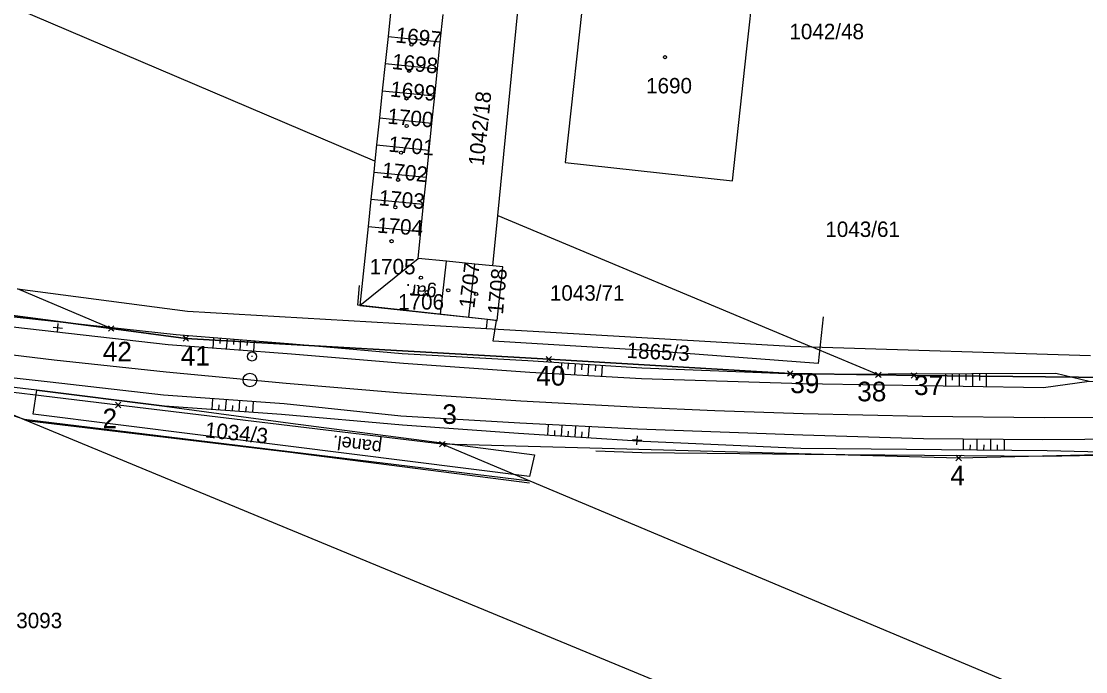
# Model space of a CAD drawing. Extents: x -779302 to -774398, y -1144902 to -1142831.
# Drawn here: x -775436.1 to -775318.8, y -1144493.5 to -1144421.9 of the extents above; entities that cross this region are included whole.
import ezdxf

# ---------------------------------------------------------------- set-up
doc = ezdxf.new("R2010")
doc.units = 0
for name, color, linetype in [('Hranice parcel', 7, 'Continuous'), ('legenda I_5_2 - Vrstva 53', 7, 'Continuous'), ('Parcelní čísla', 7, 'Continuous'), ('SŽDC', 7, 'Continuous'), ('zjednodus_g_situ-seda - Vrstva 1', 7, 'Continuous'), ('zjednodus_g_situ-seda - Vrstva 16', 7, 'Continuous'), ('zjednodus_g_situ-seda - Vrstva 17', 7, 'Continuous'), ('zjednodus_g_situ-seda - Vrstva 23', 7, 'Continuous'), ('zjednodus_g_situ-seda - Vrstva 48', 7, 'Continuous'), ('zjednodus_g_situ-seda - Vrstva 49', 7, 'Continuous'), ('zjednodus_g_situ-seda - Vrstva 59', 7, 'Continuous'), ('zjednodus_g_situ-seda - Vrstva 7', 7, 'Continuous'), ('Značky budov', 7, 'Continuous')]:
    doc.layers.add(name, color=color, linetype=linetype)

msp = doc.modelspace()

# ---------------------------------------------------------------- linework, layer by layer
at = {"layer": 'Hranice parcel'}
for p, q in [((-775383.57, -1144443.27), (-775380.75, -1144414.72)), ((-775395.35, -1144420.56), (-775395.66, -1144423.55)), ((-775389.9, -1144424.12), (-775389.59, -1144421.13)), ((-775395.66, -1144423.55), (-775395.97, -1144426.53)), ((-775395.66, -1144423.55), (-775389.9, -1144424.12)), ((-775390.2, -1144427.1), (-775389.9, -1144424.12)), ((-775395.97, -1144426.53), (-775396.29, -1144429.52)), ((-775395.97, -1144426.53), (-775390.2, -1144427.1)), ((-775390.52, -1144430.09), (-775390.2, -1144427.1)), ((-775396.29, -1144429.52), (-775396.6, -1144432.51)), ((-775396.29, -1144429.52), (-775390.52, -1144430.09)), ((-775390.82, -1144433.08), (-775390.52, -1144430.09)), ((-775396.6, -1144432.51), (-775396.92, -1144435.49)), ((-775396.6, -1144432.51), (-775390.82, -1144433.08)), ((-775391.12, -1144436.06), (-775390.82, -1144433.08)), ((-775396.92, -1144435.49), (-775397.11, -1144437.29)), ((-775396.92, -1144435.49), (-775391.12, -1144436.06)), ((-775391.44, -1144439.04), (-775391.12, -1144436.06)), ((-775397.11, -1144437.29), (-775397.23, -1144438.48)), ((-775397.23, -1144438.48), (-775397.55, -1144441.47)), ((-775397.23, -1144438.48), (-775391.44, -1144439.04)), ((-775391.74, -1144442.03), (-775391.44, -1144439.04)), ((-775397.55, -1144441.47), (-775397.86, -1144444.46)), ((-775397.55, -1144441.47), (-775391.74, -1144442.03)), ((-775392.05, -1144445.02), (-775391.74, -1144442.03)), ((-775384.12, -1144448.81), (-775383.57, -1144443.27)), ((-775383.57, -1144443.27), (-775348.99, -1144457.75)), ((-775397.86, -1144444.46), (-775398.78, -1144453.2)), ((-775397.86, -1144444.46), (-775392.05, -1144445.02)), ((-775392.35, -1144448), (-775392.05, -1144445.02)), ((-775398.78, -1144453.2), (-775392.35, -1144448)), ((-775389.23, -1144448.31), (-775392.35, -1144448)), ((-775426.17, -1144455.72), (-775474.88, -1144449.28)), ((-775389.89, -1144454.15), (-775389.23, -1144448.31)), ((-775386.1, -1144448.62), (-775389.23, -1144448.31)), ((-775386.75, -1144454.48), (-775386.1, -1144448.62)), ((-775384.12, -1144448.81), (-775386.1, -1144448.62)), ((-775426.17, -1144455.72), (-775436.47, -1144451.33)), ((-775398.78, -1144453.2), (-775389.89, -1144454.15)), ((-775389.89, -1144454.15), (-775386.75, -1144454.48)), ((-775386.75, -1144454.48), (-775384.7, -1144454.7)), ((-775384.8, -1144455.7), (-775384.7, -1144454.7)), ((-775348.99, -1144457.75), (-775318.25, -1144458.71)), ((-775341.64, -1144460.83), (-775348.99, -1144457.75)), ((-775445.43, -1144461.73), (-775435.74, -1144465.74)), ((-775380, -1144472.53), (-775435.74, -1144465.74)), ((-775435.74, -1144465.74), (-775366.41, -1144494.44)), ((-775380, -1144472.53), (-775389.68, -1144468.46)), ((-775253.51, -1144525.7), (-775380, -1144472.53))]:
    msp.add_line(p, q, dxfattribs=at)
for points in [[(-775397.11, -1144437.29), (-775575.13, -1144361.42), (-775643.03, -1144333.5), (-775681.69, -1144314.82), (-775705.2, -1144302.37), (-775726.91, -1144287.21)], [(-775355.32, -1144417.54), (-775373.75, -1144415.54), (-775373.98, -1144417.62), (-775376.13, -1144437.44), (-775357.7, -1144439.44), (-775356.16, -1144425.25), (-775355.32, -1144417.54)], [(-775384.7, -1144454.7), (-775383.62, -1144454.82), (-775383.02, -1144448.92), (-775384.12, -1144448.81)], [(-775436.47, -1144451.33), (-775417.75, -1144453.81), (-775384.8, -1144455.7)], [(-775341.64, -1144460.83), (-775351.35, -1144460.68), (-775377.95, -1144459.1), (-775417.93, -1144456.81), (-775426.17, -1144455.72)], [(-775384.8, -1144455.7), (-775377.77, -1144456.11), (-775351.31, -1144457.68), (-775348.99, -1144457.75)], [(-775254.16, -1144459.9), (-775301.48, -1144461.27), (-775337.71, -1144460.89), (-775341.64, -1144460.83)], [(-775389.68, -1144468.46), (-775425.39, -1144464.15), (-775445.43, -1144461.73)], [(-775204.62, -1144464.16), (-775217.76, -1144465.11), (-775237.91, -1144466.56), (-775289.7, -1144468.96), (-775332.79, -1144469.99), (-775389.68, -1144468.46)]]:
    msp.add_lwpolyline(points, dxfattribs=at)
at = {"layer": 'legenda I_5_2 - Vrstva 53'}
for points in [[(-775474.88, -1144449.28), (-775426.17, -1144455.72), (-775417.93, -1144456.81), (-775377.95, -1144459.1), (-775351.35, -1144460.68), (-775341.64, -1144460.83), (-775337.71, -1144460.89), (-775301.48, -1144461.27), (-775254.16, -1144459.9), (-775170.99, -1144453.66), (-775138.01, -1144449.91), (-775088.39, -1144447.82), (-775071.04, -1144440.88), (-775069.78, -1144440.38), (-775036.16, -1144437.94), (-775037.63, -1144440.85), (-775032.95, -1144440.83), (-775006.9, -1144440.82), (-775003.31, -1144440.57), (-774957.77, -1144437.47), (-774890.46, -1144432.61)], [(-774919.16, -1144442.27), (-774942.23, -1144444.12), (-775006.07, -1144448.84), (-775047.73, -1144454.47), (-775049.08, -1144458.29), (-775076.86, -1144459.23), (-775096.64, -1144457.51), (-775137.35, -1144459.01), (-775201.24, -1144463.92), (-775204.62, -1144464.16), (-775217.76, -1144465.11), (-775237.91, -1144466.56), (-775289.7, -1144468.96), (-775332.79, -1144469.99)], [(-775332.79, -1144469.99), (-775389.68, -1144468.46), (-775425.39, -1144464.15), (-775445.43, -1144461.73)]]:
    msp.add_lwpolyline(points, dxfattribs=at)
at = {"layer": 'SŽDC'}
for p, q in [((-775425.97, -1144455.92), (-775426.47, -1144455.42)), ((-775425.97, -1144455.52), (-775426.47, -1144456.02)), ((-775426.37, -1144455.92), (-775425.87, -1144455.42)), ((-775426.37, -1144455.52), (-775425.87, -1144456.02)), ((-775426.17, -1144455.72), (-775426.17, -1144455.72)), ((-775417.73, -1144457.01), (-775418.23, -1144456.51)), ((-775417.73, -1144456.61), (-775418.23, -1144457.11)), ((-775418.13, -1144457.01), (-775417.63, -1144456.51)), ((-775418.13, -1144456.61), (-775417.63, -1144457.11)), ((-775417.93, -1144456.81), (-775417.93, -1144456.81)), ((-775377.75, -1144459.3), (-775378.25, -1144458.8)), ((-775377.75, -1144458.9), (-775378.25, -1144459.4)), ((-775378.15, -1144459.3), (-775377.65, -1144458.8)), ((-775378.15, -1144458.9), (-775377.65, -1144459.4)), ((-775377.95, -1144459.1), (-775377.95, -1144459.1)), ((-775351.15, -1144460.88), (-775351.65, -1144460.38)), ((-775351.15, -1144460.48), (-775351.65, -1144460.98)), ((-775351.55, -1144460.88), (-775351.05, -1144460.38)), ((-775351.55, -1144460.48), (-775351.05, -1144460.98)), ((-775351.35, -1144460.68), (-775351.35, -1144460.68)), ((-775341.44, -1144461.03), (-775341.94, -1144460.53)), ((-775341.44, -1144460.63), (-775341.94, -1144461.13)), ((-775341.84, -1144461.03), (-775341.34, -1144460.53)), ((-775341.84, -1144460.63), (-775341.34, -1144461.13)), ((-775341.64, -1144460.83), (-775341.64, -1144460.83)), ((-775337.51, -1144461.09), (-775338.01, -1144460.59)), ((-775337.51, -1144460.69), (-775338.01, -1144461.19)), ((-775337.91, -1144461.09), (-775337.41, -1144460.59)), ((-775337.91, -1144460.69), (-775337.41, -1144461.19)), ((-775337.71, -1144460.89), (-775337.71, -1144460.89)), ((-775425.19, -1144464.35), (-775425.69, -1144463.85)), ((-775425.19, -1144463.95), (-775425.69, -1144464.45)), ((-775425.59, -1144464.35), (-775425.09, -1144463.85)), ((-775425.59, -1144463.95), (-775425.09, -1144464.45)), ((-775425.39, -1144464.15), (-775425.39, -1144464.15)), ((-775389.48, -1144468.66), (-775389.98, -1144468.16)), ((-775389.88, -1144468.66), (-775389.38, -1144468.16)), ((-775389.48, -1144468.26), (-775389.98, -1144468.76)), ((-775389.88, -1144468.26), (-775389.38, -1144468.76)), ((-775389.68, -1144468.46), (-775389.68, -1144468.46)), ((-775332.59, -1144470.19), (-775333.09, -1144469.69)), ((-775332.59, -1144469.79), (-775333.09, -1144470.29)), ((-775332.99, -1144470.19), (-775332.49, -1144469.69)), ((-775332.99, -1144469.79), (-775332.49, -1144470.29)), ((-775332.79, -1144469.99), (-775332.79, -1144469.99))]:
    msp.add_line(p, q, dxfattribs=at)
for points in [[(-775474.88, -1144449.28), (-775426.17, -1144455.72), (-775417.93, -1144456.81), (-775377.95, -1144459.1), (-775351.35, -1144460.68), (-775341.64, -1144460.83), (-775337.71, -1144460.89), (-775301.48, -1144461.27), (-775254.16, -1144459.9), (-775170.99, -1144453.66), (-775138.01, -1144449.91), (-775088.39, -1144447.82), (-775071.04, -1144440.88), (-775069.78, -1144440.38), (-775036.16, -1144437.94), (-775037.63, -1144440.85), (-775032.95, -1144440.83), (-775006.9, -1144440.82), (-775003.31, -1144440.57), (-774957.77, -1144437.47), (-774890.46, -1144432.61)], [(-774919.16, -1144442.27), (-774942.23, -1144444.12), (-775006.07, -1144448.84), (-775047.73, -1144454.47), (-775049.08, -1144458.29), (-775076.86, -1144459.23), (-775096.64, -1144457.51), (-775137.35, -1144459.01), (-775201.24, -1144463.92), (-775204.62, -1144464.16), (-775217.76, -1144465.11), (-775237.91, -1144466.56), (-775289.7, -1144468.96), (-775332.79, -1144469.99)], [(-775332.79, -1144469.99), (-775389.68, -1144468.46), (-775425.39, -1144464.15), (-775445.43, -1144461.73)]]:
    msp.add_lwpolyline(points, dxfattribs=at)
at = {"layer": 'zjednodus_g_situ-seda - Vrstva 1'}
msp.add_lwpolyline([(-775237.52, -1144462.13), (-775254.42, -1144463.35), (-775267.45, -1144464.14), (-775280.95, -1144464.78), (-775295.68, -1144465.25), (-775309.68, -1144465.5), (-775323.38, -1144465.56), (-775336.76, -1144465.43), (-775349.91, -1144465.12), (-775359.65, -1144464.79), (-775367.99, -1144464.43), (-775381.03, -1144463.72), (-775394.17, -1144462.83), (-775406.88, -1144461.77), (-775420.1, -1144460.52), (-775432.46, -1144459.19), (-775445.5, -1144457.62)], dxfattribs=at)
at = {"layer": 'zjednodus_g_situ-seda - Vrstva 16'}
msp.add_lwpolyline([(-775379.53, -1144469.62), (-775380.07, -1144472.02), (-775406.66, -1144468.68), (-775434.75, -1144465.17), (-775434.37, -1144462.51), (-775420.28, -1144464.28), (-775406.4, -1144466.16), (-775379.53, -1144469.62)], dxfattribs=at)
at = {"layer": 'zjednodus_g_situ-seda - Vrstva 17'}
for points in [[(-775529.28, -1144448.55), (-775522.23, -1144449.72), (-775493.17, -1144455.73), (-775473.92, -1144458.39), (-775448.56, -1144461.49), (-775435.18, -1144465.88), (-775406.71, -1144469.31), (-775380.06, -1144472.72)], [(-775347.72, -1144454.42), (-775348.28, -1144459.57), (-775367.69, -1144458.09), (-775384.06, -1144457.1), (-775383.71, -1144454.82)], [(-775372.78, -1144469.18), (-775367.69, -1144469.39), (-775349.72, -1144469.58), (-775323.4, -1144469.8), (-775309.65, -1144469.53), (-775280.14, -1144468.53), (-775254.41, -1144467.34), (-775237.68, -1144466.55), (-775210.39, -1144464.61), (-775186.23, -1144462.81), (-775153.25, -1144460.35), (-775137.33, -1144459.16), (-775133.83, -1144461.04)]]:
    msp.add_lwpolyline(points, dxfattribs=at)
at = {"layer": 'zjednodus_g_situ-seda - Vrstva 23'}
msp.add_lwpolyline([(-775383.71, -1144454.82), (-775398.99, -1144453.13), (-775398.8, -1144450.97)], dxfattribs=at)
at = {"layer": 'zjednodus_g_situ-seda - Vrstva 48'}
for p, q in [((-775414.89, -1144456.74), (-775414.98, -1144457.88)), ((-775414.14, -1144456.8), (-775414.19, -1144457.37)), ((-775413.4, -1144456.86), (-775413.49, -1144457.99)), ((-775412.65, -1144456.92), (-775412.69, -1144457.48)), ((-775411.9, -1144456.98), (-775411.99, -1144458.1)), ((-775411.15, -1144457.04), (-775411.2, -1144457.6)), ((-775410.41, -1144457.1), (-775410.5, -1144458.21)), ((-775376.55, -1144459.53), (-775376.63, -1144460.77)), ((-775375.8, -1144459.58), (-775375.84, -1144460.19)), ((-775375.06, -1144459.62), (-775375.13, -1144460.85)), ((-775374.31, -1144459.67), (-775374.35, -1144460.28)), ((-775373.56, -1144459.72), (-775373.64, -1144460.93)), ((-775372.81, -1144459.77), (-775372.85, -1144460.37)), ((-775372.06, -1144459.81), (-775372.14, -1144461.02)), ((-775334.25, -1144460.73), (-775334.25, -1144462.09)), ((-775333.5, -1144460.73), (-775333.5, -1144461.41)), ((-775332.75, -1144460.73), (-775332.75, -1144462.11)), ((-775332, -1144460.72), (-775332, -1144461.42)), ((-775331.25, -1144460.72), (-775331.25, -1144462.14)), ((-775330.5, -1144460.71), (-775330.5, -1144461.43)), ((-775329.75, -1144460.71), (-775329.75, -1144462.16)), ((-775415.05, -1144464.65), (-775414.96, -1144463.45)), ((-775414.3, -1144464.71), (-775414.26, -1144464.11)), ((-775413.55, -1144464.76), (-775413.47, -1144463.56)), ((-775412.81, -1144464.81), (-775412.76, -1144464.21)), ((-775412.06, -1144464.87), (-775411.97, -1144463.66)), ((-775411.31, -1144464.92), (-775411.27, -1144464.32)), ((-775410.56, -1144464.97), (-775410.47, -1144463.77)), ((-775378.05, -1144467.48), (-775377.98, -1144466.31)), ((-775377.3, -1144467.53), (-775377.27, -1144466.94)), ((-775376.56, -1144467.58), (-775376.48, -1144466.39)), ((-775375.06, -1144467.67), (-775374.98, -1144466.46)), ((-775373.56, -1144467.77), (-775373.48, -1144466.54)), ((-775375.81, -1144467.62), (-775375.77, -1144467.02)), ((-775374.31, -1144467.72), (-775374.27, -1144467.11)), ((-775332.26, -1144469.12), (-775332.25, -1144467.91)), ((-775330.76, -1144469.13), (-775330.75, -1144467.92)), ((-775329.26, -1144469.15), (-775329.25, -1144467.94)), ((-775327.76, -1144469.16), (-775327.75, -1144467.96)), ((-775331.51, -1144469.13), (-775331.5, -1144468.52)), ((-775330.01, -1144469.14), (-775330, -1144468.54)), ((-775328.51, -1144469.16), (-775328.5, -1144468.55))]:
    msp.add_line(p, q, dxfattribs=at)
at = {"layer": 'zjednodus_g_situ-seda - Vrstva 49'}
for points in [[(-775318.42, -1144461.57), (-775323.45, -1144462.27), (-775349.98, -1144461.82), (-775367.73, -1144461.27), (-775380.03, -1144460.58), (-775393.96, -1144459.59), (-775406.28, -1144458.53), (-775419.87, -1144457.52), (-775444.78, -1144454.69), (-775470.55, -1144451.14), (-775484.05, -1144449.34), (-775495.6, -1144447.28), (-775508.81, -1144445.09), (-775521.66, -1144442.4), (-775533.53, -1144439.91), (-775545.11, -1144437.29), (-775560.56, -1144433.46), (-775571.96, -1144430.35)], [(-775154.54, -1144453.28), (-775157.07, -1144452.49), (-775186.45, -1144454.65), (-775211.52, -1144456.52), (-775233.72, -1144457.95), (-775237.78, -1144458.55), (-775254.76, -1144459.94), (-775280.65, -1144460.69), (-775309.64, -1144461.82), (-775318.42, -1144461.57), (-775322.08, -1144460.68), (-775349.82, -1144460.8), (-775367.7, -1144460.09), (-775380.25, -1144459.29), (-775394.11, -1144458.5), (-775406.17, -1144457.44), (-775418.99, -1144456.41), (-775444.62, -1144453.63), (-775470, -1144450.13), (-775494.73, -1144446.53), (-775521.32, -1144441), (-775544.98, -1144436.05), (-775571.96, -1144430.35)], [(-775136.47, -1144457.15), (-775137.33, -1144459.16), (-775153.73, -1144459.62), (-775186.34, -1144461.91), (-775210.44, -1144464), (-775236.37, -1144465.85), (-775254.41, -1144467.34), (-775280.14, -1144468.53), (-775309.65, -1144469.53), (-775323.06, -1144469.21), (-775350.17, -1144468.93), (-775367.56, -1144468.16), (-775381.28, -1144467.27), (-775394.06, -1144466.38), (-775407.39, -1144465.2), (-775420.28, -1144464.28), (-775434.37, -1144462.51), (-775445.82, -1144461.16), (-775472.35, -1144457.73), (-775493.63, -1144454.24), (-775521.94, -1144448.83), (-775534.74, -1144446.19), (-775546.66, -1144443.43), (-775573.95, -1144436.42)], [(-775136.47, -1144457.15), (-775153.96, -1144458.51), (-775186.33, -1144460.94), (-775211.22, -1144462.57), (-775237.32, -1144464.61), (-775254.56, -1144465.91), (-775267.94, -1144466.41), (-775280.22, -1144467.25), (-775295.79, -1144467.75), (-775309.6, -1144467.88), (-775323.53, -1144468), (-775336.67, -1144467.86), (-775349.95, -1144467.46), (-775368.17, -1144466.82), (-775381.15, -1144466.14), (-775394.24, -1144465.36), (-775407.1, -1144464.01), (-775420.38, -1144463.07), (-775432.89, -1144461.62), (-775445.78, -1144460.2)]]:
    msp.add_lwpolyline(points, dxfattribs=at)
at = {"layer": 'zjednodus_g_situ-seda - Vrstva 59'}
msp.add_circle((-775391.4, -1144451.72), 0.175, dxfattribs=at)
at = {"layer": 'zjednodus_g_situ-seda - Vrstva 7'}
for p, q in [((-775432.09, -1144456.15), (-775431.99, -1144455.15)), ((-775431.54, -1144455.7), (-775432.54, -1144455.6)), ((-775410.59, -1144458.8), (-775410.69, -1144458.79)), ((-775367.71, -1144468.05), (-775368.71, -1144468)), ((-775368.24, -1144468.53), (-775368.18, -1144467.53))]:
    msp.add_line(p, q, dxfattribs=at)
for centre, radius in [((-775410.64, -1144458.8), 0.5), ((-775410.88, -1144461.39), 0.75)]:
    msp.add_circle(centre, radius, dxfattribs=at)
at = {"layer": 'Značky budov'}
for centre in [(-775393.07, -1144424.44), (-775365.15, -1144425.82), (-775393.33, -1144427.33), (-775393.63, -1144430.37), (-775393.61, -1144433.41), (-775394.23, -1144436.34), (-775394.55, -1144439.34), (-775394.85, -1144442.36), (-775395.27, -1144446.1), (-775392.04, -1144450.12), (-775389.03, -1144451.51), (-775385.95, -1144451.92)]:
    msp.add_circle(centre, 0.175, dxfattribs=at)

# ---------------------------------------------------------------- texts
at = {"layer": 'Parcelní čísla'}
for s, p in [('1042/48', (-775351.44, -1144423.84)), ('1690', (-775367.23, -1144429.81)), ('1043/61', (-775347.48, -1144445.63)), ('1705', (-775397.69, -1144449.75)), ('1043/71', (-775377.83, -1144452.65)), ('1706', (-775394.55, -1144453.63)), ('3093', (-775436.62, -1144488.74))]:
    msp.add_text(s, height=1.7, dxfattribs=at).set_placement(p)
for s, rotation, p in [('1697', 354, (-775394.88, -1144424.19)), ('1698', 354, (-775395.29, -1144427.11)), ('1699', 354, (-775395.48, -1144430.14)), ('1042/18', 84, (-775385.12, -1144437.85)), ('1700', 355, (-775395.78, -1144433.14)), ('1701', 355, (-775395.67, -1144436.22)), ('1702', 354, (-775396.4, -1144439.08)), ('1703', 355, (-775396.74, -1144442.13)), ('1704', 356, (-775396.91, -1144445.15)), ('1707', 83, (-775386.16, -1144453.55)), ('1708', 85, (-775383, -1144454.21)), ('1865/3', 357, (-775369.41, -1144458.95)), ('1034/3', 354, (-775415.9, -1144467.7))]:
    msp.add_text(s, height=1.7, rotation=rotation, dxfattribs=at).set_placement(p)
at = {"layer": 'SŽDC'}
for s, p in [('42', (-775427.09, -1144459.34)), ('41', (-775418.5, -1144459.8)), ('40', (-775379.33, -1144462.01)), ('39', (-775351.35, -1144462.84)), ('37', (-775337.71, -1144463.05)), ('38', (-775343.97, -1144463.74)), ('2', (-775427.11, -1144466.71)), ('3', (-775389.68, -1144466.23)), ('4', (-775333.71, -1144472.98))]:
    msp.add_text(s, height=2.16, dxfattribs=at).set_placement(p)
at = {"layer": 'zjednodus_g_situ-seda - Vrstva 16'}
msp.add_text('panel.', height=1.5, rotation=172.8262, dxfattribs=at).set_placement((-775396.27, -1144468.16))
at = {"layer": 'zjednodus_g_situ-seda - Vrstva 23'}
msp.add_text('gar.', height=1.5, rotation=173.68, dxfattribs=at).set_placement((-775390.27, -1144451.16))

doc.saveas('drawing.dxf')
